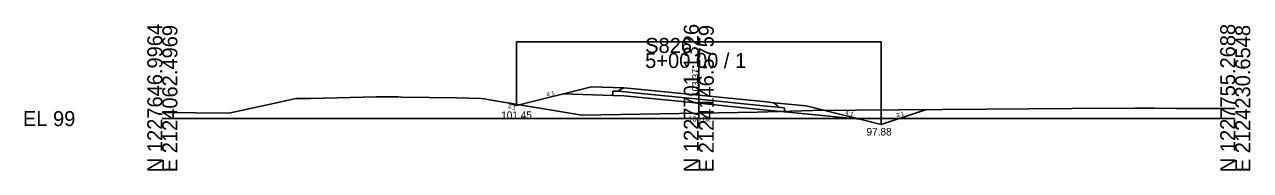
# Model space of a CAD drawing. Extents: x 2118382 to 2118616, y 1213030 to 1222057.
# Drawn here: x 2118381.9 to 2118610.4, y 1215530.1 to 1215557.4 of the extents above; entities that cross this region are included whole.
import ezdxf

# ---------------------------------------------------------------- set-up
doc = ezdxf.new("R2010")
doc.units = 0
for name, color, linetype in [('XS_CELL', 7, 'Continuous'), ('XS_M_DITCH', 7, 'Continuous'), ('XS_P_FINISHED_GRADE', 7, 'Continuous'), ('XS_P_FINISHED_GRADE_ELEV_TX', 7, 'Continuous'), ('XS_P_SUBGRADE_GRANULAR', 7, 'Continuous'), ('XS_P_SUBGRADE_PAVEMENT', 7, 'Continuous'), ('XS_P_TX_DCH', 7, 'Continuous'), ('XS_P_TX_FS_BS', 7, 'Continuous'), ('XS_X_GROUND', 7, 'Continuous'), ('XS_X_GROUND_TX', 7, 'Continuous')]:
    doc.layers.add(name, color=color, linetype=linetype)

msp = doc.modelspace()

# ---------------------------------------------------------------- linework, layer by layer
at = {"layer": 'XS_CELL'}
for p, q in [((2118507.6, 1215539.8), (2118507.6, 1215552.06)), ((2118407.6, 1215539.8), (2118507.6, 1215539.8)), ((2118507.6, 1215539.8), (2118607.6, 1215539.8))]:
    msp.add_line(p, q, dxfattribs=at)
at = {"layer": 'XS_M_DITCH'}
for p, q in [((2118473.6, 1215542.26), (2118473.6, 1215554.17)), ((2118473.6, 1215554.17), (2118541.6, 1215554.17)), ((2118541.6, 1215538.68), (2118541.6, 1215554.17))]:
    msp.add_line(p, q, dxfattribs=at)
at = {"layer": 'XS_P_FINISHED_GRADE'}
for p, q in [((2118487.6, 1215545.75), (2118473.6, 1215542.26)), ((2118493.6, 1215545.57), (2118487.6, 1215545.75)), ((2118495.6, 1215545.37), (2118493.6, 1215545.57)), ((2118495.6, 1215545.37), (2118507.6, 1215544.17)), ((2118473.6, 1215542.26), (2118472.16, 1215542.74)), ((2118507.6, 1215544.17), (2118519.6, 1215542.97)), ((2118519.6, 1215542.97), (2118521.6, 1215542.77)), ((2118521.6, 1215542.77), (2118527.6, 1215542.17)), ((2118527.6, 1215542.17), (2118541.6, 1215538.68)), ((2118541.6, 1215538.68), (2118550.02, 1215541.48))]:
    msp.add_line(p, q, dxfattribs=at)
at = {"layer": 'XS_P_SUBGRADE_GRANULAR'}
for p, q in [((2118491.6, 1215544.13), (2118482.24, 1215544.41)), ((2118491.6, 1215544.13), (2118491.6, 1215544.95)), ((2118492.71, 1215544.91), (2118491.6, 1215544.95)), ((2118493.6, 1215544.07), (2118491.6, 1215544.13)), ((2118495.6, 1215543.87), (2118493.6, 1215544.07)), ((2118495.6, 1215543.87), (2118507.6, 1215542.67)), ((2118507.6, 1215542.67), (2118519.6, 1215541.47)), ((2118519.6, 1215541.47), (2118521.6, 1215541.27)), ((2118521.6, 1215541.27), (2118523.6, 1215541.07)), ((2118522.42, 1215541.94), (2118523.6, 1215541.82)), ((2118523.6, 1215541.07), (2118523.6, 1215541.82)), ((2118523.6, 1215541.07), (2118537.63, 1215539.67))]:
    msp.add_line(p, q, dxfattribs=at)
at = {"layer": 'XS_P_SUBGRADE_PAVEMENT'}
for p, q in [((2118492.87, 1215545.19), (2118492.71, 1215544.91)), ((2118495.6, 1215544.62), (2118492.71, 1215544.91)), ((2118493.6, 1215545.57), (2118492.87, 1215545.19)), ((2118495.6, 1215544.62), (2118507.6, 1215543.42)), ((2118507.6, 1215543.42), (2118519.6, 1215542.22)), ((2118519.6, 1215542.22), (2118522.42, 1215541.94)), ((2118521.6, 1215542.77), (2118522.24, 1215542.25)), ((2118522.24, 1215542.25), (2118522.42, 1215541.94))]:
    msp.add_line(p, q, dxfattribs=at)
at = {"layer": 'XS_X_GROUND'}
for p, q in [((2118420, 1215540.79), (2118428.32, 1215542.63)), ((2118428.32, 1215542.63), (2118432.47, 1215543.56)), ((2118432.47, 1215543.56), (2118435.25, 1215543.58)), ((2118435.25, 1215543.58), (2118447.44, 1215543.86)), ((2118447.44, 1215543.86), (2118448.52, 1215543.89)), ((2118448.52, 1215543.89), (2118451.57, 1215543.84)), ((2118451.57, 1215543.84), (2118452.19, 1215543.83)), ((2118452.19, 1215543.83), (2118462.48, 1215543.67)), ((2118462.48, 1215543.67), (2118466.97, 1215543.53)), ((2118466.97, 1215543.53), (2118467.62, 1215543.51)), ((2118467.62, 1215543.51), (2118468.96, 1215543.27)), ((2118468.96, 1215543.27), (2118485.78, 1215540.45)), ((2118407.6, 1215540.92), (2118420, 1215540.79)), ((2118485.78, 1215540.45), (2118507.6, 1215540.82)), ((2118507.6, 1215540.82), (2118518.48, 1215541.01)), ((2118518.48, 1215541.01), (2118528.86, 1215541.34)), ((2118528.86, 1215541.34), (2118577.21, 1215541.67)), ((2118577.21, 1215541.67), (2118588.88, 1215541.73)), ((2118588.88, 1215541.73), (2118592.52, 1215541.74)), ((2118592.52, 1215541.74), (2118596.6, 1215541.72)), ((2118596.6, 1215541.72), (2118607.6, 1215541.69))]:
    msp.add_line(p, q, dxfattribs=at)

# ---------------------------------------------------------------- texts
at = {"layer": 'XS_CELL'}
for s, p in [('N 1227646.9964', (2118407.6, 1215529.8)), ('E 2124062.4969', (2118410.4, 1215529.8)), ('N 1227701.1326', (2118507.6, 1215529.8)), ('E 2124146.5759', (2118510.4, 1215529.8)), ('N 1227755.2688', (2118607.6, 1215529.8)), ('E 2124230.6548', (2118610.4, 1215529.8))]:
    msp.add_text(s, height=2.8, rotation=90, dxfattribs=at).set_placement(p)
for s, p in [('S826', (2118497.6, 1215552.06)), ('5+00.00 / 1', (2118497.6, 1215549.26)), ('EL 99', (2118381.6, 1215538.4))]:
    msp.add_text(s, height=2.8, dxfattribs=at).set_placement(p)
at = {"layer": 'XS_P_FINISHED_GRADE_ELEV_TX'}
msp.add_text('103.37', height=1.25, rotation=90, dxfattribs=at).set_placement((2118507.6, 1215543.98))
at = {"layer": 'XS_P_TX_DCH'}
for s, p in [('101.45', (2118470.76, 1215539.75)), ('97.88', (2118538.86, 1215536.65))]:
    msp.add_text(s, height=1.4, dxfattribs=at).set_placement(p)
at = {"layer": 'XS_P_TX_FS_BS'}
for s, rotation, p in [('4:1', 14.0188, (2118479.3, 1215543.88)), ('3:1', 341.5651, (2118471.92, 1215541.87)), ('3:1', 341.5651, (2118471.92, 1215541.87)), ('4:1', 345.9847, (2118534.85, 1215540.6)), ('3:1', 18.4082, (2118544.5, 1215539.98))]:
    msp.add_text(s, height=0.8, rotation=rotation, dxfattribs=at).set_placement(p)
at = {"layer": 'XS_X_GROUND_TX'}
msp.add_text('100.02', height=1, dxfattribs=at).set_placement((2118505.66, 1215539.21))

doc.saveas('drawing.dxf')
